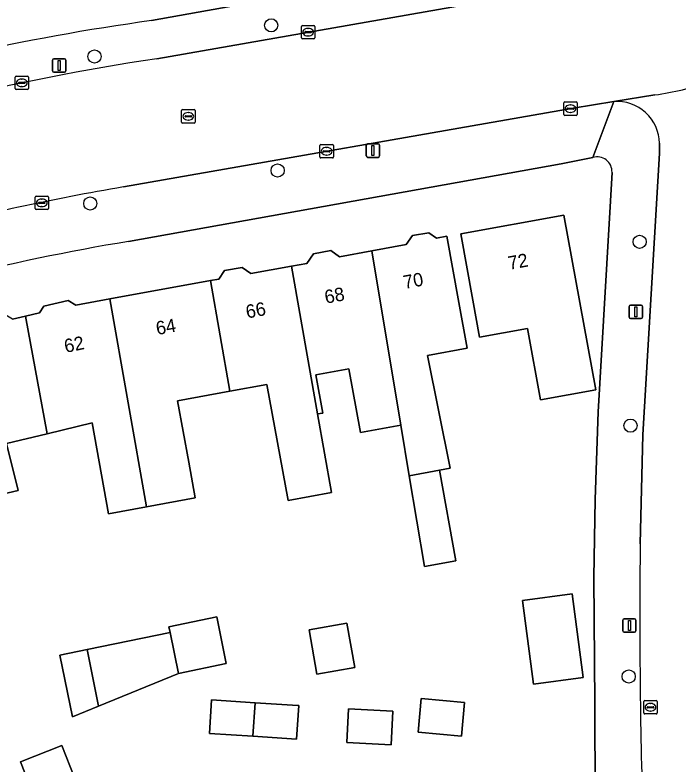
# Model space of a CAD drawing. Extents: x 160157 to 160921, y 381516 to 382045.
# Drawn here: x 160448.3 to 160497.6, y 381667.9 to 381723.6 of the extents above; entities that cross this region are included whole.
import ezdxf

# ---------------------------------------------------------------- set-up
doc = ezdxf.new("R2010")
doc.units = 0
for name, color, linetype in [('IMGEO_Boom', 7, 'Continuous'), ('IMGEO_Erf', 7, 'Continuous'), ('IMGEO_Fietspad_gesloten', 7, 'Continuous'), ('IMGEO_Kolk', 7, 'Continuous'), ('IMGEO_Lichtmast', 7, 'Continuous'), ('IMGEO_Pand', 7, 'Continuous'), ('IMGEO_Pand_nummerreeks', 7, 'Continuous'), ('IMGEO_Rijbaan_lokaal_open', 7, 'Continuous'), ('IMGEO_Rioolput', 7, 'Continuous'), ('IMGEO_Voetpad_open', 7, 'Continuous')]:
    doc.layers.add(name, color=color, linetype=linetype)

msp = doc.modelspace()

# ---------------------------------------------------------------- linework, layer by layer
at = {"layer": 'IMGEO_Boom'}
for centre in [(160467.376, 381722.867), (160454.233, 381720.544), (160467.852, 381712.068), (160453.913, 381709.617), (160494.786, 381706.768), (160494.105, 381693.092), (160493.971, 381674.431)]:
    msp.add_circle(centre, 0.489, dxfattribs=at)
at = {"layer": 'IMGEO_Erf'}
for points in [[(160458.476, 381723.221), (160493.473, 381729.503)], [(160491.301, 381713.031), (160488.939, 381712.571), (160456.756, 381706.79)], [(160491.686, 381661.452), (160491.512, 381666.491), (160491.457, 381669.708), (160491.439, 381672.439), (160491.376, 381681.789), (160491.463, 381687.593), (160491.694, 381694.13), (160492.728, 381711.927)], [(160448.132, 381701.004), (160449.102, 381701.24), (160450.142, 381701.493), (160450.465, 381701.968), (160452.276, 381702.407), (160452.849, 381702.058), (160455.375, 381702.519), (160462.861, 381703.883), (160463.467, 381703.994), (160463.902, 381704.623), (160465.205, 381704.861), (160465.868, 381704.402), (160468.876, 381704.95), (160470.026, 381705.16), (160470.522, 381705.878), (160471.8, 381706.111), (160472.461, 381705.653), (160474.864, 381706.091), (160477.421, 381706.557), (160477.881, 381707.222), (160479.091, 381707.443), (160479.679, 381707.037), (160480.431, 381707.174), (160481.328, 381702.256), (160481.948, 381698.853), (160478.995, 381698.316), (160480.681, 381689.919), (160479.891, 381689.775), (160481.12, 381683.031), (160478.777, 381682.604), (160477.65, 381689.366), (160477.024, 381693.124), (160474.017, 381692.576), (160473.152, 381697.321), (160470.696, 381696.873), (160471.214, 381694.031), (160470.813, 381693.958), (160471.858, 381688.116), (160468.629, 381687.527), (160467.056, 381696.152), (160464.307, 381695.651), (160460.407, 381694.94), (160461.239, 381690.38), (160461.726, 381687.71), (160458.107, 381687.05), (160455.278, 381686.534), (160454.043, 381693.302), (160450.715, 381692.494), (160447.693, 381691.76), (160448.541, 381688.27), (160445.555, 381687.569)]]:
    msp.add_lwpolyline(points, dxfattribs=at)
for points in [[(160486.445, 381700.325), (160482.874, 381699.674), (160482.371, 381702.432), (160481.475, 381707.35), (160489.156, 381708.75), (160491.523, 381695.767), (160487.412, 381695.018)], [(160486.057, 381680.096), (160489.759, 381680.586), (160490.582, 381674.363), (160486.881, 381673.873)], [(160451.645, 381676.028), (160453.675, 381676.442), (160459.857, 381677.704), (160459.769, 381678.135), (160463.318, 381678.859), (160464.025, 381675.392), (160460.477, 381674.668), (160454.534, 381672.231), (160452.583, 381671.431)], [(160470.189, 381677.911), (160473.01, 381678.4), (160473.584, 381675.09), (160470.763, 381674.601)], [(160462.925, 381672.703), (160466.173, 381672.486), (160469.367, 381672.273), (160469.42, 381672.269), (160469.266, 381669.769), (160466.019, 381669.986), (160462.771, 381670.203)], [(160478.526, 381672.788), (160481.762, 381672.487), (160481.531, 381669.996), (160478.295, 381670.296)], [(160473.129, 381672.022), (160476.415, 381671.863), (160476.295, 381669.361), (160473.009, 381669.52)], [(160448.731, 381668.089), (160451.793, 381669.293), (160452.709, 381666.961), (160449.647, 381665.758)]]:
    msp.add_lwpolyline(points, close=True, dxfattribs=at)
for centre, radius, start, end in [((160482.422, 381550.627), 174.247, 97.89878, 102.62823), ((160491.629, 381711.98), 1.101, 357.2182, 107.3271), ((160482.134, 381552.43), 156.433, 99.33628, 109.29985)]:
    msp.add_arc(centre, radius, start, end, dxfattribs=at)
at = {"layer": 'IMGEO_Fietspad_gesloten'}
for points in [[(160495.923, 381717.689), (160492.872, 381717.206)], [(160496.263, 381714.092), (160496.253, 381713.363), (160495.016, 381692.409), (160494.828, 381684.31)]]:
    msp.add_lwpolyline(points, dxfattribs=at)
for centre, radius, start, end in [((160490.5, 381751.904), 34.642, 279.0068, 285.9168), ((160493.075, 381714.023), 3.189, 1.2334, 93.6433), ((160961.225, 381678.785), 466.43, 179.32125, 181.81004)]:
    msp.add_arc(centre, radius, start, end, dxfattribs=at)
at = {"layer": 'IMGEO_Kolk'}
for p, q in [((160469.619, 381721.936), (160469.619, 381722.788)), ((160469.694, 381722.862), (160470.546, 381722.862)), ((160470.62, 381722.788), (160470.62, 381721.936)), ((160469.878, 381722.356), (160469.878, 381722.368)), ((160470.316, 381722.319), (160469.918, 381722.319)), ((160469.921, 381722.405), (160470.319, 381722.405)), ((160470.107, 381722.642), (160470.132, 381722.642)), ((160470.362, 381722.368), (160470.362, 381722.356)), ((160470.546, 381721.862), (160469.694, 381721.862)), ((160470.13, 381722.082), (160470.105, 381722.082)), ((160448.32, 381718.164), (160448.32, 381719.016)), ((160448.395, 381719.09), (160449.247, 381719.09)), ((160448.808, 381718.87), (160448.833, 381718.87)), ((160449.321, 381719.016), (160449.321, 381718.164)), ((160448.579, 381718.584), (160448.579, 381718.596)), ((160449.017, 381718.547), (160448.619, 381718.547)), ((160448.622, 381718.633), (160449.02, 381718.633)), ((160448.831, 381718.31), (160448.806, 381718.31)), ((160449.063, 381718.596), (160449.063, 381718.584)), ((160449.247, 381718.09), (160448.395, 381718.09)), ((160489.212, 381717.169), (160490.064, 381717.169)), ((160489.137, 381716.243), (160489.137, 381717.095)), ((160489.396, 381716.663), (160489.396, 381716.675)), ((160489.834, 381716.626), (160489.436, 381716.626)), ((160489.439, 381716.712), (160489.837, 381716.712)), ((160489.625, 381716.949), (160489.65, 381716.949)), ((160489.88, 381716.675), (160489.88, 381716.663)), ((160490.138, 381717.095), (160490.138, 381716.243)), ((160490.064, 381716.169), (160489.212, 381716.169)), ((160489.648, 381716.389), (160489.623, 381716.389)), ((160470.999, 381713.075), (160470.999, 381713.927)), ((160471.074, 381714.001), (160471.926, 381714.001)), ((160472, 381713.927), (160472, 381713.075)), ((160471.258, 381713.495), (160471.258, 381713.507)), ((160471.696, 381713.458), (160471.298, 381713.458)), ((160471.301, 381713.544), (160471.699, 381713.544)), ((160471.487, 381713.781), (160471.512, 381713.781)), ((160471.742, 381713.507), (160471.742, 381713.495)), ((160471.926, 381713.001), (160471.074, 381713.001)), ((160471.51, 381713.221), (160471.485, 381713.221)), ((160449.806, 381709.239), (160449.806, 381710.091)), ((160449.881, 381710.165), (160450.733, 381710.165)), ((160450.294, 381709.945), (160450.319, 381709.945)), ((160450.807, 381710.091), (160450.807, 381709.239)), ((160450.065, 381709.659), (160450.065, 381709.671)), ((160450.503, 381709.622), (160450.105, 381709.622)), ((160450.108, 381709.708), (160450.506, 381709.708)), ((160450.317, 381709.385), (160450.292, 381709.385)), ((160450.549, 381709.671), (160450.549, 381709.659)), ((160450.733, 381709.165), (160449.881, 381709.165))]:
    msp.add_line(p, q, dxfattribs=at)
for points in [[(160469.619, 381721.936), (160469.619, 381722.788)], [(160469.694, 381722.862), (160470.546, 381722.862)], [(160470.62, 381722.788), (160470.62, 381721.936)], [(160470.546, 381721.862), (160469.694, 381721.862)], [(160448.32, 381718.164), (160448.32, 381719.016)], [(160448.395, 381719.09), (160449.247, 381719.09)], [(160449.321, 381719.016), (160449.321, 381718.164)], [(160449.247, 381718.09), (160448.395, 381718.09)], [(160489.212, 381717.169), (160490.064, 381717.169)], [(160489.137, 381716.243), (160489.137, 381717.095)], [(160490.138, 381717.095), (160490.138, 381716.243)], [(160490.064, 381716.169), (160489.212, 381716.169)], [(160470.999, 381713.075), (160470.999, 381713.927)], [(160471.074, 381714.001), (160471.926, 381714.001)], [(160472, 381713.927), (160472, 381713.075)], [(160471.926, 381713.001), (160471.074, 381713.001)], [(160449.806, 381709.239), (160449.806, 381710.091)], [(160449.881, 381710.165), (160450.733, 381710.165)], [(160450.807, 381710.091), (160450.807, 381709.239)], [(160450.733, 381709.165), (160449.881, 381709.165)]]:
    msp.add_lwpolyline(points, dxfattribs=at)
for centre, radius, start, end in [((160469.696, 381722.786), 0.0765, 91.552, 178.448), ((160469.696, 381722.786), 0.0765, 91.552, 178.448), ((160470.544, 381722.786), 0.0765, 1.552, 88.448), ((160470.544, 381722.786), 0.0765, 1.552, 88.448), ((160469.918, 381722.365), 0.0403, 85.8775, 175.7526), ((160469.915, 381722.355), 0.0366, 178.938, 274.7102), ((160470.319, 381722.362), 0.043, 264.8664, 352.4533), ((160470.323, 381722.367), 0.0386, 1.7309, 96.639), ((160469.696, 381721.938), 0.0765, 181.552, 268.448), ((160469.696, 381721.938), 0.0765, 181.552, 268.448), ((160470.544, 381721.938), 0.0765, 271.552, 358.448), ((160470.544, 381721.938), 0.0765, 271.552, 358.448), ((160448.397, 381719.014), 0.0765, 91.552, 178.448), ((160448.397, 381719.014), 0.0765, 91.552, 178.448), ((160449.245, 381719.014), 0.0765, 1.552, 88.448), ((160449.245, 381719.014), 0.0765, 1.552, 88.448), ((160448.619, 381718.593), 0.0403, 85.8775, 175.7526), ((160448.616, 381718.583), 0.0366, 178.938, 274.7102), ((160449.02, 381718.59), 0.043, 264.8664, 352.4533), ((160449.024, 381718.595), 0.0386, 1.7309, 96.639), ((160448.397, 381718.166), 0.0765, 181.552, 268.448), ((160448.397, 381718.166), 0.0765, 181.552, 268.448), ((160449.245, 381718.166), 0.0765, 271.552, 358.448), ((160449.245, 381718.166), 0.0765, 271.552, 358.448), ((160489.214, 381717.093), 0.0765, 91.552, 178.448), ((160489.214, 381717.093), 0.0765, 91.552, 178.448), ((160490.062, 381717.093), 0.0765, 1.552, 88.448), ((160490.062, 381717.093), 0.0765, 1.552, 88.448), ((160489.436, 381716.672), 0.0403, 85.8775, 175.7526), ((160489.433, 381716.662), 0.0366, 178.938, 274.7102), ((160489.837, 381716.669), 0.043, 264.8664, 352.4533), ((160489.841, 381716.674), 0.0386, 1.7309, 96.639), ((160489.214, 381716.245), 0.0765, 181.552, 268.448), ((160489.214, 381716.245), 0.0765, 181.552, 268.448), ((160490.062, 381716.245), 0.0765, 271.552, 358.448), ((160490.062, 381716.245), 0.0765, 271.552, 358.448), ((160471.076, 381713.925), 0.0765, 91.552, 178.448), ((160471.076, 381713.925), 0.0765, 91.552, 178.448), ((160471.924, 381713.925), 0.0765, 1.552, 88.448), ((160471.924, 381713.925), 0.0765, 1.552, 88.448), ((160471.298, 381713.504), 0.0403, 85.8775, 175.7526), ((160471.295, 381713.494), 0.0366, 178.938, 274.7102), ((160471.699, 381713.501), 0.043, 264.8664, 352.4533), ((160471.703, 381713.506), 0.0386, 1.7309, 96.639), ((160471.076, 381713.077), 0.0765, 181.552, 268.448), ((160471.076, 381713.077), 0.0765, 181.552, 268.448), ((160471.924, 381713.077), 0.0765, 271.552, 358.448), ((160471.924, 381713.077), 0.0765, 271.552, 358.448), ((160449.883, 381710.089), 0.0765, 91.552, 178.448), ((160449.883, 381710.089), 0.0765, 91.552, 178.448), ((160450.731, 381710.089), 0.0765, 1.552, 88.448), ((160450.731, 381710.089), 0.0765, 1.552, 88.448), ((160450.105, 381709.668), 0.0403, 85.8775, 175.7526), ((160450.102, 381709.658), 0.0366, 178.938, 274.7102), ((160450.506, 381709.665), 0.043, 264.8664, 352.4533), ((160450.51, 381709.67), 0.0386, 1.7309, 96.639), ((160449.883, 381709.241), 0.0765, 181.552, 268.448), ((160449.883, 381709.241), 0.0765, 181.552, 268.448), ((160450.731, 381709.241), 0.0765, 271.552, 358.448), ((160450.731, 381709.241), 0.0765, 271.552, 358.448)]:
    msp.add_arc(centre, radius, start, end, dxfattribs=at)
for centre, major_axis, ratio, start_param, end_param in [((160470.106, 381722.362), (-0.387, 0.002), 0.722429, 4.712389, 7.853982), ((160470.131, 381722.362), (-0.39, 0.002), 0.717154, 1.570796, 4.712389), ((160448.807, 381718.59), (-0.387, 0.002), 0.722429, 4.712389, 7.853982), ((160448.832, 381718.59), (-0.39, 0.002), 0.717154, 1.570796, 4.712389), ((160489.624, 381716.669), (-0.387, 0.002), 0.722429, 4.712389, 7.853982), ((160489.649, 381716.669), (-0.39, 0.002), 0.717154, 1.570796, 4.712389), ((160471.486, 381713.501), (-0.387, 0.002), 0.722429, 4.712389, 7.853982), ((160471.511, 381713.501), (-0.39, 0.002), 0.717154, 1.570796, 4.712389), ((160450.293, 381709.665), (-0.387, 0.002), 0.722429, 4.712389, 7.853982), ((160450.318, 381709.665), (-0.39, 0.002), 0.717154, 1.570796, 4.712389)]:
    msp.add_ellipse(centre, major_axis=major_axis, ratio=ratio, start_param=start_param, end_param=end_param, dxfattribs=at)
at = {"layer": 'IMGEO_Lichtmast'}
for p, q in [((160451.103, 381719.484), (160451.103, 381720.284)), ((160451.103, 381720.284), (160451.103, 381719.484)), ((160451.203, 381720.384), (160451.993, 381720.384)), ((160451.993, 381720.384), (160451.203, 381720.384)), ((160452.093, 381720.284), (160452.093, 381719.484)), ((160452.093, 381719.484), (160452.093, 381720.284)), ((160451.993, 381719.384), (160451.203, 381719.384)), ((160451.203, 381719.384), (160451.993, 381719.384)), ((160474.447, 381713.148), (160474.447, 381713.948)), ((160474.447, 381713.948), (160474.447, 381713.148)), ((160474.547, 381714.048), (160475.337, 381714.048)), ((160475.337, 381714.048), (160474.547, 381714.048)), ((160475.437, 381713.948), (160475.437, 381713.148)), ((160475.437, 381713.148), (160475.437, 381713.948)), ((160475.337, 381713.048), (160474.547, 381713.048)), ((160474.547, 381713.048), (160475.337, 381713.048)), ((160494.005, 381701.153), (160494.005, 381701.953)), ((160494.005, 381701.953), (160494.005, 381701.153)), ((160494.105, 381702.053), (160494.895, 381702.053)), ((160494.895, 381702.053), (160494.105, 381702.053)), ((160494.995, 381701.953), (160494.995, 381701.153)), ((160494.995, 381701.153), (160494.995, 381701.953)), ((160494.895, 381701.053), (160494.105, 381701.053)), ((160494.105, 381701.053), (160494.895, 381701.053)), ((160493.623, 381678.723), (160494.413, 381678.723)), ((160494.413, 381678.723), (160493.623, 381678.723)), ((160493.523, 381677.823), (160493.523, 381678.623)), ((160493.523, 381678.623), (160493.523, 381677.823)), ((160494.513, 381678.623), (160494.513, 381677.823)), ((160494.513, 381677.823), (160494.513, 381678.623)), ((160494.413, 381677.723), (160493.623, 381677.723)), ((160493.623, 381677.723), (160494.413, 381677.723))]:
    msp.add_line(p, q, dxfattribs=at)
for points in [[(160451.523, 381720.259), (160451.673, 381720.259), (160451.673, 381719.509), (160451.523, 381719.509), (160451.523, 381720.259)], [(160474.867, 381713.923), (160475.017, 381713.923), (160475.017, 381713.173), (160474.867, 381713.173), (160474.867, 381713.923)], [(160494.425, 381701.928), (160494.575, 381701.928), (160494.575, 381701.178), (160494.425, 381701.178), (160494.425, 381701.928)], [(160493.943, 381678.598), (160494.093, 381678.598), (160494.093, 381677.848), (160493.943, 381677.848), (160493.943, 381678.598)]]:
    msp.add_lwpolyline(points, dxfattribs=at)
for centre, start, end in [((160451.203, 381720.284), 90, 180), ((160451.203, 381720.284), 90, 180), ((160451.993, 381720.284), 0, 90), ((160451.993, 381720.284), 360, 90), ((160451.203, 381719.484), 180, 270), ((160451.203, 381719.484), 180, 270), ((160451.993, 381719.484), 270, 0), ((160451.993, 381719.484), 270, 0), ((160474.547, 381713.948), 90, 180), ((160474.547, 381713.948), 90, 180), ((160475.337, 381713.948), 0, 90), ((160475.337, 381713.948), 360, 90), ((160474.547, 381713.148), 180, 270), ((160474.547, 381713.148), 180, 270), ((160475.337, 381713.148), 270, 0), ((160475.337, 381713.148), 270, 0), ((160494.105, 381701.953), 90, 180), ((160494.105, 381701.953), 90, 180), ((160494.895, 381701.953), 0, 90), ((160494.895, 381701.953), 360, 90), ((160494.105, 381701.153), 180, 270), ((160494.105, 381701.153), 180, 270), ((160494.895, 381701.153), 270, 0), ((160494.895, 381701.153), 270, 0), ((160493.623, 381678.623), 90, 180), ((160493.623, 381678.623), 90, 180), ((160494.413, 381678.623), 0, 90), ((160494.413, 381678.623), 360, 90), ((160493.623, 381677.823), 180, 270), ((160493.623, 381677.823), 180, 270), ((160494.413, 381677.823), 270, 0), ((160494.413, 381677.823), 270, 0)]:
    msp.add_arc(centre, 0.1, start, end, dxfattribs=at)
at = {"layer": 'IMGEO_Pand'}
for points in [[(160487.412, 381695.018), (160491.523, 381695.767), (160489.156, 381708.75), (160481.475, 381707.35), (160482.371, 381702.432), (160482.874, 381699.674), (160486.445, 381700.325)], [(160478.995, 381698.316), (160481.948, 381698.853), (160481.328, 381702.256), (160480.431, 381707.174), (160479.679, 381707.037), (160479.091, 381707.443), (160477.881, 381707.222), (160477.421, 381706.557), (160474.864, 381706.091), (160477.024, 381693.124), (160477.65, 381689.366), (160479.891, 381689.775), (160480.681, 381689.919)], [(160474.864, 381706.091), (160472.461, 381705.653), (160471.8, 381706.111), (160470.522, 381705.878), (160470.026, 381705.16), (160468.876, 381704.95), (160470.813, 381693.958), (160471.214, 381694.031), (160470.696, 381696.873), (160473.152, 381697.321), (160474.017, 381692.576), (160477.024, 381693.124)], [(160468.876, 381704.95), (160465.868, 381704.402), (160465.205, 381704.861), (160463.902, 381704.623), (160463.467, 381703.994), (160462.861, 381703.883), (160464.307, 381695.651), (160467.056, 381696.152), (160468.629, 381687.527), (160471.858, 381688.116), (160470.813, 381693.958)], [(160455.375, 381702.519), (160458.107, 381687.05), (160461.726, 381687.71), (160461.239, 381690.38), (160460.407, 381694.94), (160464.307, 381695.651), (160462.861, 381703.883)], [(160455.375, 381702.519), (160452.849, 381702.058), (160452.276, 381702.407), (160450.465, 381701.968), (160450.142, 381701.493), (160449.102, 381701.24), (160450.715, 381692.494), (160454.043, 381693.302), (160455.278, 381686.534), (160458.107, 381687.05)], [(160445.555, 381687.569), (160448.541, 381688.27), (160447.693, 381691.76), (160450.715, 381692.494), (160449.102, 381701.24), (160448.132, 381701.004), (160447.507, 381701.385), (160445.697, 381700.946), (160445.406, 381700.354), (160442.595, 381699.671), (160443.775, 381694.813)], [(160479.891, 381689.775), (160477.65, 381689.366), (160478.777, 381682.604), (160481.12, 381683.031)], [(160486.881, 381673.873), (160490.582, 381674.363), (160489.759, 381680.586), (160486.057, 381680.096)], [(160459.857, 381677.704), (160460.477, 381674.668), (160464.025, 381675.392), (160463.318, 381678.859), (160459.769, 381678.135)], [(160470.763, 381674.601), (160473.584, 381675.09), (160473.01, 381678.4), (160470.189, 381677.911)], [(160459.857, 381677.704), (160453.675, 381676.442), (160454.534, 381672.231), (160460.477, 381674.668)], [(160453.675, 381676.442), (160451.645, 381676.028), (160452.583, 381671.431), (160454.534, 381672.231)], [(160466.173, 381672.486), (160462.925, 381672.703), (160462.771, 381670.203), (160466.019, 381669.986)], [(160481.762, 381672.487), (160478.526, 381672.788), (160478.295, 381670.296), (160481.531, 381669.996)], [(160469.42, 381672.269), (160469.367, 381672.273), (160466.173, 381672.486), (160466.019, 381669.986), (160469.266, 381669.769)], [(160476.415, 381671.863), (160473.129, 381672.022), (160473.009, 381669.52), (160476.295, 381669.361)], [(160451.793, 381669.293), (160448.731, 381668.089), (160449.647, 381665.758), (160452.709, 381666.961)]]:
    msp.add_lwpolyline(points, close=True, dxfattribs=at)
at = {"layer": 'IMGEO_Rijbaan_lokaal_open'}
for points in [[(160507.42, 381730.147), (160495.166, 381726.612), (160495.077, 381726.768), (160494.319, 381726.608), (160490.606, 381725.966), (160488.392, 381725.543), (160484.206, 381724.841), (160458.857, 381720.382)], [(160456.391, 381710.843), (160489.831, 381716.702), (160492.872, 381717.206), (160495.923, 381717.689)]]:
    msp.add_lwpolyline(points, dxfattribs=at)
for centre, radius, start, end in [((160487.124, 381533.441), 189.066, 98.59859, 108.43577), ((160490.5, 381751.904), 34.642, 279.0068, 285.9168), ((160485.365, 381539.107), 174.163, 99.57623, 104.81005)]:
    msp.add_arc(centre, radius, start, end, dxfattribs=at)
at = {"layer": 'IMGEO_Rioolput'}
for p, q in [((160460.705, 381715.672), (160460.705, 381716.524)), ((160460.78, 381716.598), (160461.632, 381716.598)), ((160460.964, 381716.092), (160460.964, 381716.104)), ((160461.402, 381716.055), (160461.004, 381716.055)), ((160461.007, 381716.141), (160461.405, 381716.141)), ((160461.193, 381716.378), (160461.218, 381716.378)), ((160461.448, 381716.104), (160461.448, 381716.092)), ((160461.706, 381716.524), (160461.706, 381715.672)), ((160461.632, 381715.598), (160460.78, 381715.598)), ((160461.216, 381715.818), (160461.191, 381715.818)), ((160495.164, 381672.645), (160496.016, 381672.645)), ((160495.089, 381671.719), (160495.089, 381672.571)), ((160495.348, 381672.139), (160495.348, 381672.151)), ((160495.786, 381672.102), (160495.388, 381672.102)), ((160495.391, 381672.188), (160495.789, 381672.188)), ((160495.577, 381672.425), (160495.602, 381672.425)), ((160495.832, 381672.151), (160495.832, 381672.139)), ((160496.09, 381672.571), (160496.09, 381671.719)), ((160496.016, 381671.645), (160495.164, 381671.645)), ((160495.6, 381671.865), (160495.575, 381671.865))]:
    msp.add_line(p, q, dxfattribs=at)
for points in [[(160460.705, 381715.672), (160460.705, 381716.524)], [(160460.78, 381716.598), (160461.632, 381716.598)], [(160461.706, 381716.524), (160461.706, 381715.672)], [(160461.632, 381715.598), (160460.78, 381715.598)], [(160495.164, 381672.645), (160496.016, 381672.645)], [(160495.089, 381671.719), (160495.089, 381672.571)], [(160496.09, 381672.571), (160496.09, 381671.719)], [(160496.016, 381671.645), (160495.164, 381671.645)]]:
    msp.add_lwpolyline(points, dxfattribs=at)
for centre, radius, start, end in [((160460.782, 381716.522), 0.0765, 91.552, 178.448), ((160460.782, 381716.522), 0.0765, 91.552, 178.448), ((160461.004, 381716.101), 0.0403, 85.8775, 175.7526), ((160461.001, 381716.091), 0.0366, 178.938, 274.7102), ((160461.405, 381716.098), 0.043, 264.8664, 352.4533), ((160461.409, 381716.103), 0.0386, 1.7309, 96.639), ((160461.63, 381716.522), 0.0765, 1.552, 88.448), ((160461.63, 381716.522), 0.0765, 1.552, 88.448), ((160460.782, 381715.674), 0.0765, 181.552, 268.448), ((160460.782, 381715.674), 0.0765, 181.552, 268.448), ((160461.63, 381715.674), 0.0765, 271.552, 358.448), ((160461.63, 381715.674), 0.0765, 271.552, 358.448), ((160495.166, 381672.569), 0.0765, 91.552, 178.448), ((160495.166, 381672.569), 0.0765, 91.552, 178.448), ((160496.014, 381672.569), 0.0765, 1.552, 88.448), ((160496.014, 381672.569), 0.0765, 1.552, 88.448), ((160495.388, 381672.148), 0.0403, 85.8775, 175.7526), ((160495.385, 381672.138), 0.0366, 178.938, 274.7102), ((160495.789, 381672.145), 0.043, 264.8664, 352.4533), ((160495.793, 381672.15), 0.0386, 1.7309, 96.639), ((160495.166, 381671.721), 0.0765, 181.552, 268.448), ((160495.166, 381671.721), 0.0765, 181.552, 268.448), ((160496.014, 381671.721), 0.0765, 271.552, 358.448), ((160496.014, 381671.721), 0.0765, 271.552, 358.448)]:
    msp.add_arc(centre, radius, start, end, dxfattribs=at)
for centre, major_axis, ratio, start_param, end_param in [((160461.192, 381716.098), (-0.387, 0.002), 0.722429, 4.712389, 7.853982), ((160461.217, 381716.098), (-0.39, 0.002), 0.717154, 1.570796, 4.712389), ((160495.576, 381672.145), (-0.387, 0.002), 0.722429, 4.712389, 7.853982), ((160495.601, 381672.145), (-0.39, 0.002), 0.717154, 1.570796, 4.712389)]:
    msp.add_ellipse(centre, major_axis=major_axis, ratio=ratio, start_param=start_param, end_param=end_param, dxfattribs=at)
at = {"layer": 'IMGEO_Voetpad_open'}
for points in [[(160497.042, 381728.693), (160497.426, 381730.148), (160497.459, 381730.97), (160497.464, 381731.201), (160493.473, 381729.503), (160458.476, 381723.221)], [(160458.857, 381720.382), (160484.206, 381724.841), (160488.392, 381725.543), (160490.606, 381725.966), (160494.319, 381726.608), (160495.077, 381726.768)], [(160456.756, 381706.79), (160488.939, 381712.571), (160491.301, 381713.031), (160492.872, 381717.206), (160489.831, 381716.702), (160456.391, 381710.843)], [(160492.872, 381717.206), (160491.301, 381713.031)], [(160496.253, 381713.363), (160496.263, 381714.092)], [(160494.828, 381684.31), (160495.016, 381692.409), (160496.253, 381713.363)], [(160492.728, 381711.927), (160491.694, 381694.13), (160491.463, 381687.593), (160491.376, 381681.789), (160491.439, 381672.439), (160491.457, 381669.708), (160491.512, 381666.491), (160491.686, 381661.452)]]:
    msp.add_lwpolyline(points, dxfattribs=at)
for centre, radius, start, end in [((160482.422, 381550.627), 174.247, 97.89878, 102.62823), ((160487.124, 381533.441), 189.066, 98.59859, 108.43577), ((160493.075, 381714.023), 3.189, 1.2334, 93.6433), ((160491.629, 381711.98), 1.101, 357.2182, 107.3271), ((160485.365, 381539.107), 174.163, 99.57623, 104.81005), ((160482.134, 381552.43), 156.433, 99.33628, 109.29985), ((160961.225, 381678.785), 466.43, 179.32125, 181.81004)]:
    msp.add_arc(centre, radius, start, end, dxfattribs=at)

# ---------------------------------------------------------------- texts
at = {"layer": 'IMGEO_Pand_nummerreeks'}
for s, rotation, p in [('72', 10.3298, (160485.088, 381704.674)), ('70', 10.6054, (160477.296, 381703.25)), ('68', 10.6054, (160471.44, 381702.153)), ('66', 10.6054, (160465.58, 381701.055)), ('64', 10.3333, (160458.893, 381699.825)), ('62', 11.5206, (160452.08, 381698.5))]:
    msp.add_text(s, height=1, rotation=rotation, dxfattribs=at).set_placement(p)

doc.saveas('drawing.dxf')
